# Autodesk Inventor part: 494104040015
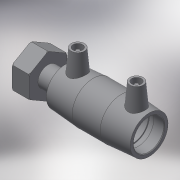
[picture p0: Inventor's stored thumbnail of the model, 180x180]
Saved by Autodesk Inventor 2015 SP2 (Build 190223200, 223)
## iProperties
Created: 2017-06
Part Number: 494104040015
Material: Generic
Description: PLASSON FEMALE FREE NUT TRANSITION COUPLER 40X 1½
Document SubType Name: Modeling
Designer: KIM
Mass: 55.0731 g
Surface Area: 148.067 cm^2
Volume: 55.0731 cm^3
Density: 1 g/cm^3
Appearance: Default
Author: KIM
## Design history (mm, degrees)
derived "494104.ipt"
feature "Solid1::494104.ipt"
tag "TaggingFeature1"
body "Solid1"
other parameters: "d0" = 97, "d2" = 56, "d3" = 47, "d4" = 32.33333, "d5" = 50.4, "d6" = 38, "d8" = 168 deg, "d10" = 18.8, "d11" = 6.26667, "d29" = 45, "d30" = 14, "d31" = 33.95, "d34" = 5 deg, "d41" = 4, "d42" = 14, "d43" = 0, "d48" = 3, "d49" = 0, "d55" = 38, "d57" = 29, "d80" = 0.8, "d83" = 19, "d84" = 12.54, "d85" = 1.254, "d86" = 35.876, "d87" = 44.845, "d88" = 67.2675, "d89" = 56, "d90" = 1.34535, "d94" = 0, "d95" = 1.254, "d96" = 31.3915, "L_" = 135, "L_1" = 47, "D_1" = 56, "A_" = 45, "d_2" = 12, "L_2" = 38, "D_" = 29, "G_" = 44.845
